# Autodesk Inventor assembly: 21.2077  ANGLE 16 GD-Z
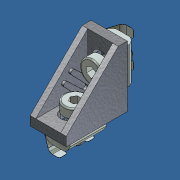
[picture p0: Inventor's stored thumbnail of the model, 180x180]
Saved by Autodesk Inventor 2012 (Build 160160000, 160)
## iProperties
Created: 2014-03
Part Number: 21.2077  ANGLE 16 GD-Z
Document SubType Name: Assembly
Designer: Admin
Author: Admin
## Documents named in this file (4)
- C:\Andys Backup Data\ANDY'S INVENTOR\INVENTOR LIBRARIES\PARTS LIBRARY\30 SERIES\21.2077  ANGLE 16 GD-Z.iam
- C:\Andys Backup Data\ANDY'S INVENTOR\INVENTOR LIBRARIES\PARTS LIBRARY\30 SERIES\SUBCOMPONENTS\21.2077_1  ANGLE 16 GD-Z.ipt
- C:\Andys Backup Data\ANDY'S INVENTOR\INVENTOR LIBRARIES\PARTS LIBRARY\FASTENING ELEMENTS\SCREWS CAP\21.1143 M6X12.ipt
- C:\Andys Backup Data\ANDY'S INVENTOR\INVENTOR LIBRARIES\PARTS LIBRARY\30 SERIES\21.1569 M6 SQUARE NUT 30 POS FXG.ipt
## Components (5 placed, 3 different names)
1. 21.2077_1  ANGLE 16 GD-Z:1 — Mate:1, Mate:2, Mate:3, Mate:4, Mate:5, Mate:6, Mate:8, Angle:1, Mate:10, Angle:2
2. 21.1143 M6 x 12:1 — Mate:1, Mate:2, Mate:3, Mate:9
3. 21.1143 M6 x 12:2 — Mate:4, Mate:5, Mate:6, Mate:7
4. 21.1569 M6 SQUARE NUT 30 POS FXG:1 — Mate:7, Mate:8, Angle:1
5. 21.1569 M6 SQUARE NUT 30 POS FXG:2 — Mate:9, Mate:10, Angle:2
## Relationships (12: Mate 10, Angle 2)
- Mate:1: 21.2077_1  ANGLE 16 GD-Z:1 ↔ 21.1143 M6 x 12:1
- Mate:2: 21.2077_1  ANGLE 16 GD-Z:1 ↔ 21.1143 M6 x 12:1
- Mate:3: 21.2077_1  ANGLE 16 GD-Z:1 ↔ 21.1143 M6 x 12:1
- Mate:4: 21.2077_1  ANGLE 16 GD-Z:1 ↔ 21.1143 M6 x 12:2
- Mate:5: 21.2077_1  ANGLE 16 GD-Z:1 ↔ 21.1143 M6 x 12:2
- Mate:6: 21.2077_1  ANGLE 16 GD-Z:1 ↔ 21.1143 M6 x 12:2
- Mate:7: 21.1143 M6 x 12:2 ↔ 21.1569 M6 SQUARE NUT 30 POS FXG:1
- Mate:8: 21.2077_1  ANGLE 16 GD-Z:1 ↔ 21.1569 M6 SQUARE NUT 30 POS FXG:1
- Angle:1: 21.2077_1  ANGLE 16 GD-Z:1 ↔ 21.1569 M6 SQUARE NUT 30 POS FXG:1
- Mate:9: 21.1143 M6 x 12:1 ↔ 21.1569 M6 SQUARE NUT 30 POS FXG:2
- Mate:10: 21.2077_1  ANGLE 16 GD-Z:1 ↔ 21.1569 M6 SQUARE NUT 30 POS FXG:2
- Angle:2: 21.2077_1  ANGLE 16 GD-Z:1 ↔ 21.1569 M6 SQUARE NUT 30 POS FXG:2
